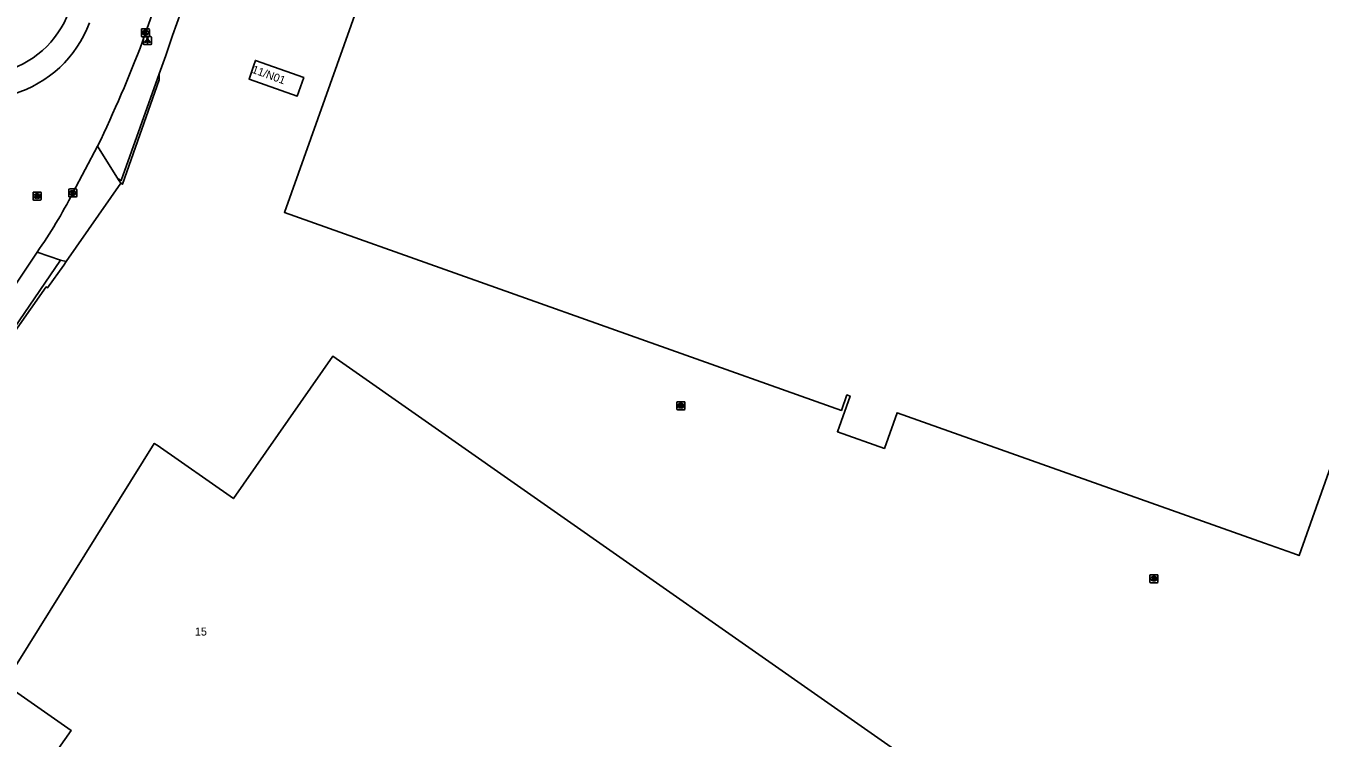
# Model space of a CAD drawing. Extents: x 155018 to 156648, y 383980 to 385733.
# Drawn here: x 155664.5 to 155826.1, y 384797.2 to 384886.2 of the extents above; entities that cross this region are included whole.
import ezdxf

# ---------------------------------------------------------------- set-up
doc = ezdxf.new("R2010")
doc.units = 0
for name, color, linetype in [('IMGEO_Brandkraan', 7, 'Continuous'), ('IMGEO_Groenvoorziening', 7, 'Continuous'), ('IMGEO_Hek', 7, 'Continuous'), ('IMGEO_Kolk', 7, 'Continuous'), ('IMGEO_Lichtpunt', 7, 'Continuous'), ('IMGEO_Pand', 7, 'Continuous'), ('IMGEO_Pand_nummerreeks', 7, 'Continuous'), ('IMGEO_Rijbaan_lokaal_gesloten', 7, 'Continuous'), ('IMGEO_Rijbaan_lokaal_open', 7, 'Continuous'), ('IMGEO_Rioolput', 7, 'Continuous'), ('IMGEO_Voetpad_open', 7, 'Continuous')]:
    doc.layers.add(name, color=color, linetype=linetype)

msp = doc.modelspace()

# ---------------------------------------------------------------- linework, layer by layer
at = {"layer": 'IMGEO_Brandkraan'}
for p, q in [((155745.8, 384838.34), (155745.8, 384839.2)), ((155745.87, 384839.27), (155746.72, 384839.27)), ((155746.28, 384839.05), (155746.31, 384839.05)), ((155746.8, 384839.2), (155746.8, 384838.34)), ((155746.72, 384838.27), (155745.87, 384838.27)), ((155746.31, 384838.49), (155746.28, 384838.49)), ((155804.89, 384816.73), (155804.89, 384817.58)), ((155804.96, 384817.66), (155805.82, 384817.66)), ((155805.82, 384816.66), (155804.96, 384816.66)), ((155805.4, 384816.88), (155805.37, 384816.88)), ((155805.38, 384817.44), (155805.4, 384817.44)), ((155805.89, 384817.58), (155805.89, 384816.73))]:
    msp.add_line(p, q, dxfattribs=at)
for points in [[(155745.8, 384838.34), (155745.8, 384839.2)], [(155745.87, 384839.27), (155746.72, 384839.27)], [(155746.8, 384839.2), (155746.8, 384838.34)], [(155746.72, 384838.27), (155745.87, 384838.27)], [(155746.14, 384838.97), (155746.14, 384838.57), (155746.36, 384838.57)], [(155746.37, 384838.97), (155746.14, 384838.97)], [(155746.32, 384838.89), (155746.27, 384838.89), (155746.27, 384838.81)], [(155746.27, 384838.81), (155746.32, 384838.81)], [(155746.33, 384838.74), (155746.27, 384838.74), (155746.27, 384838.65)], [(155746.27, 384838.65), (155746.33, 384838.65)], [(155804.89, 384816.73), (155804.89, 384817.58)], [(155804.96, 384817.66), (155805.82, 384817.66)], [(155805.82, 384816.66), (155804.96, 384816.66)], [(155805.24, 384817.36), (155805.24, 384816.96), (155805.45, 384816.96)], [(155805.47, 384817.36), (155805.24, 384817.36)], [(155805.42, 384817.27), (155805.36, 384817.27), (155805.36, 384817.2)], [(155805.36, 384817.2), (155805.42, 384817.2)], [(155805.42, 384817.12), (155805.36, 384817.12), (155805.36, 384817.04)], [(155805.36, 384817.04), (155805.42, 384817.04)], [(155805.89, 384817.58), (155805.89, 384816.73)]]:
    msp.add_lwpolyline(points, dxfattribs=at)
for centre, radius, start, end in [((155745.87, 384839.19), 0.0765, 91.552, 178.448), ((155745.87, 384839.19), 0.0765, 91.552, 178.448), ((155746.72, 384839.19), 0.0765, 1.552, 88.448), ((155746.72, 384839.19), 0.0765, 1.552, 88.448), ((155745.87, 384838.34), 0.0765, 181.552, 268.448), ((155745.87, 384838.34), 0.0765, 181.552, 268.448), ((155746.32, 384838.85), 0.0379, 267.8285, 90.9355), ((155746.33, 384838.7), 0.0404, 269.8759, 90.5077), ((155746.36, 384838.82), 0.251, 268.6676, 293.5347), ((155746.38, 384838.82), 0.145, 59.4692, 91.5367), ((155746.4, 384838.87), 0.0922, 285.5137, 58.1501), ((155746.41, 384838.68), 0.105, 301.3115, 78.989), ((155746.72, 384838.34), 0.0765, 271.552, 358.448), ((155746.72, 384838.34), 0.0765, 271.552, 358.448), ((155804.97, 384817.58), 0.0765, 91.552, 178.448), ((155804.97, 384817.58), 0.0765, 91.552, 178.448), ((155804.97, 384816.73), 0.0765, 181.552, 268.448), ((155804.97, 384816.73), 0.0765, 181.552, 268.448), ((155805.42, 384817.24), 0.0379, 267.8285, 90.9355), ((155805.42, 384817.08), 0.0404, 269.8759, 90.5077), ((155805.46, 384817.21), 0.251, 268.6676, 293.5347), ((155805.47, 384817.21), 0.145, 59.4692, 91.5367), ((155805.5, 384817.26), 0.0922, 285.5137, 58.1501), ((155805.5, 384817.07), 0.105, 301.3115, 78.989), ((155805.81, 384817.58), 0.0765, 1.552, 88.448), ((155805.81, 384817.58), 0.0765, 1.552, 88.448), ((155805.81, 384816.73), 0.0765, 271.552, 358.448), ((155805.81, 384816.73), 0.0765, 271.552, 358.448)]:
    msp.add_arc(centre, radius, start, end, dxfattribs=at)
for centre, major_axis, ratio, start_param, end_param in [((155746.28, 384838.77), (-0.387, 0.002), 0.722429, 4.712389, 7.853982), ((155746.31, 384838.77), (-0.39, 0.002), 0.717154, 1.570796, 4.712389), ((155805.38, 384817.16), (-0.387, 0.002), 0.722429, 4.712389, 7.853982), ((155805.4, 384817.16), (-0.39, 0.002), 0.717154, 1.570796, 4.712389)]:
    msp.add_ellipse(centre, major_axis=major_axis, ratio=ratio, start_param=start_param, end_param=end_param, dxfattribs=at)
at = {"layer": 'IMGEO_Groenvoorziening'}
for points in [[(155681.14, 384880.23), (155681.15, 384879.52), (155676.55, 384866.45), (155676.35, 384866.58)], [(155669.5, 384856.8), (155669.21, 384856.33), (155667.2, 384853.51), (155667.02, 384853.62), (155588.11, 384741.16), (155588.22, 384741.11), (155586.79, 384739.09), (155582.63, 384733.19), (155582.42, 384732.89), (155582.32, 384732.95)]]:
    msp.add_lwpolyline(points, dxfattribs=at)
at = {"layer": 'IMGEO_Hek'}
for points in [[(155681.15, 384879.52), (155676.55, 384866.45), (155676.35, 384866.58)], [(155676.35, 384866.58), (155669.5, 384856.8)], [(155586.79, 384739.09), (155588.22, 384741.11), (155588.11, 384741.16), (155667.02, 384853.62), (155667.2, 384853.51), (155669.21, 384856.33)], [(155669.5, 384856.8), (155669.21, 384856.33)]]:
    msp.add_lwpolyline(points, dxfattribs=at)
at = {"layer": 'IMGEO_Kolk'}
for p, q in [((155678.91, 384884.96), (155678.91, 384885.81)), ((155678.98, 384885.89), (155679.83, 384885.89)), ((155679.83, 384884.89), (155678.98, 384884.89)), ((155679.42, 384885.11), (155679.39, 384885.11)), ((155679.4, 384885.67), (155679.42, 384885.67)), ((155679.91, 384885.81), (155679.91, 384884.96)), ((155669.84, 384864.95), (155669.84, 384865.8)), ((155669.91, 384865.87), (155670.76, 384865.87)), ((155670.32, 384865.65), (155670.35, 384865.65)), ((155670.35, 384865.09), (155670.32, 384865.09)), ((155670.84, 384865.8), (155670.84, 384864.95)), ((155670.76, 384864.87), (155669.91, 384864.87))]:
    msp.add_line(p, q, dxfattribs=at)
for points in [[(155678.91, 384884.96), (155678.91, 384885.81)], [(155678.98, 384885.89), (155679.83, 384885.89)], [(155679.83, 384884.89), (155678.98, 384884.89)], [(155679.23, 384885.59), (155679.35, 384885.59), (155679.35, 384885.43), (155679.48, 384885.59), (155679.65, 384885.59), (155679.5, 384885.44), (155679.65, 384885.19), (155679.5, 384885.19), (155679.42, 384885.35), (155679.35, 384885.28), (155679.35, 384885.19), (155679.23, 384885.19), (155679.23, 384885.59)], [(155679.91, 384885.81), (155679.91, 384884.96)], [(155669.84, 384864.95), (155669.84, 384865.8)], [(155669.91, 384865.87), (155670.76, 384865.87)], [(155670.16, 384865.57), (155670.28, 384865.57), (155670.28, 384865.42), (155670.41, 384865.57), (155670.57, 384865.57), (155670.43, 384865.42), (155670.58, 384865.17), (155670.43, 384865.17), (155670.34, 384865.34), (155670.28, 384865.27), (155670.28, 384865.17), (155670.16, 384865.17), (155670.16, 384865.57)], [(155670.84, 384865.8), (155670.84, 384864.95)], [(155670.76, 384864.87), (155669.91, 384864.87)]]:
    msp.add_lwpolyline(points, dxfattribs=at)
for centre, start, end in [((155678.98, 384885.81), 91.552, 178.448), ((155678.98, 384885.81), 91.552, 178.448), ((155678.98, 384884.96), 181.552, 268.448), ((155678.98, 384884.96), 181.552, 268.448), ((155679.83, 384885.81), 1.552, 88.448), ((155679.83, 384885.81), 1.552, 88.448), ((155679.83, 384884.96), 271.552, 358.448), ((155679.83, 384884.96), 271.552, 358.448), ((155669.91, 384865.8), 91.552, 178.448), ((155669.91, 384865.8), 91.552, 178.448), ((155669.91, 384864.95), 181.552, 268.448), ((155669.91, 384864.95), 181.552, 268.448), ((155670.76, 384865.8), 1.552, 88.448), ((155670.76, 384865.8), 1.552, 88.448), ((155670.76, 384864.95), 271.552, 358.448), ((155670.76, 384864.95), 271.552, 358.448)]:
    msp.add_arc(centre, 0.0765, start, end, dxfattribs=at)
for centre, major_axis, ratio, start_param, end_param in [((155679.39, 384885.39), (-0.387, 0.002), 0.722429, 4.712389, 7.853982), ((155679.42, 384885.39), (-0.39, 0.002), 0.717154, 1.570796, 4.712389), ((155670.32, 384865.37), (-0.387, 0.002), 0.722429, 4.712389, 7.853982), ((155670.35, 384865.37), (-0.39, 0.002), 0.717154, 1.570796, 4.712389)]:
    msp.add_ellipse(centre, major_axis=major_axis, ratio=ratio, start_param=start_param, end_param=end_param, dxfattribs=at)
at = {"layer": 'IMGEO_Lichtpunt'}
for p, q in [((155679.17, 384884.8), (155679.17, 384883.99)), ((155679.17, 384884.8), (155679.17, 384883.99)), ((155680.08, 384884.9), (155679.27, 384884.9)), ((155680.08, 384884.9), (155679.27, 384884.9)), ((155680.17, 384883.99), (155680.17, 384884.8)), ((155680.17, 384883.99), (155680.17, 384884.8)), ((155679.27, 384883.9), (155680.08, 384883.9)), ((155679.27, 384883.9), (155680.08, 384883.9))]:
    msp.add_line(p, q, dxfattribs=at)
for points in [[(155679.55, 384884.46), (155679.59, 384884.44), (155679.4, 384884.17), (155679.36, 384884.2), (155679.55, 384884.46)], [(155679.65, 384884.42), (155679.7, 384884.42), (155679.7, 384884.09), (155679.65, 384884.09), (155679.65, 384884.42)], [(155679.76, 384884.44), (155679.8, 384884.46), (155679.99, 384884.2), (155679.95, 384884.17), (155679.76, 384884.44)]]:
    msp.add_lwpolyline(points, dxfattribs=at)
msp.add_circle((155679.67, 384884.6), 0.0994, dxfattribs=at)
for centre, start, end in [((155679.27, 384884.8), 90, 180), ((155679.27, 384884.8), 90, 180), ((155680.08, 384884.8), 0, 90), ((155680.08, 384884.8), 0, 90), ((155679.27, 384883.99), 180, 270), ((155679.27, 384883.99), 180, 270), ((155680.08, 384883.99), 270, 0), ((155680.08, 384883.99), 270, 360)]:
    msp.add_arc(centre, 0.0946, start, end, dxfattribs=at)
at = {"layer": 'IMGEO_Pand'}
for points in [[(155762.36, 385042.82), (155753.18, 385017), (155750.62, 385009.8), (155749.14, 385010.33), (155747.33, 385005.28), (155748.84, 385004.77), (155746.3, 384997.64), (155740.17, 384980.4), (155728.92, 384948.72), (155727.47, 384949.23), (155696.77, 384862.93), (155766.35, 384838.19), (155767.04, 384840.13), (155767.44, 384839.98), (155765.85, 384835.53), (155771.73, 384833.45), (155773.3, 384837.89), (155819.22, 384821.59), (155822.73, 384820.34), (155823.53, 384820.05), (155825.2, 384824.77), (155840.07, 384866.64)], [(155698.98, 384879.19), (155698.38, 384877.48), (155692.36, 384879.59), (155692.96, 384881.34), (155693.16, 384881.93), (155699.2, 384879.79), (155698.98, 384879.19)], [(155662.83, 384787.79), (155670.12, 384798.2), (155661.81, 384804.02), (155680.52, 384834.07), (155680.89, 384833.83), (155690.4, 384827.18), (155702.83, 384844.99), (155791.89, 384782.58)]]:
    msp.add_lwpolyline(points, dxfattribs=at)
at = {"layer": 'IMGEO_Rijbaan_lokaal_gesloten'}
for points in [[(155679.06, 384884.31), (155679.41, 384885.39), (155683.08, 384895.66), (155693.32, 384923.96)], [(155670.34, 384865.37), (155673.44, 384871.22)], [(155586.29, 384744.21), (155590.34, 384750), (155608.17, 384775.45), (155620.85, 384793.57), (155634.39, 384812.92), (155647.78, 384831.99), (155658, 384846.57), (155663.29, 384854.1), (155665.55, 384857.45), (155665.87, 384857.97)]]:
    msp.add_lwpolyline(points, dxfattribs=at)
for centre, radius, start, end in [((155658.65, 384891.78), 14.7, 286.9163, 339.3861), ((155522.65, 384943.7), 167.31, 334.3268, 339.2063), ((155617.4, 384892.23), 59.36, 324.7466, 333.1009)]:
    msp.add_arc(centre, radius, start, end, dxfattribs=at)
at = {"layer": 'IMGEO_Rijbaan_lokaal_open'}
for points in [[(155673.44, 384871.22), (155676.05, 384866.99)], [(155676.35, 384866.58), (155669.5, 384856.8)], [(155676.05, 384866.99), (155676.35, 384866.58)], [(155665.87, 384857.97), (155668.82, 384856.95)], [(155668.82, 384856.95), (155669.5, 384856.8)]]:
    msp.add_lwpolyline(points, dxfattribs=at)
at = {"layer": 'IMGEO_Rioolput'}
for p, q in [((155665.38, 384864.54), (155665.38, 384865.39)), ((155665.46, 384865.47), (155666.31, 384865.47)), ((155665.87, 384865.25), (155665.9, 384865.25)), ((155666.38, 384865.39), (155666.38, 384864.54)), ((155666.31, 384864.47), (155665.46, 384864.47)), ((155665.89, 384864.69), (155665.87, 384864.69))]:
    msp.add_line(p, q, dxfattribs=at)
for points in [[(155665.38, 384864.54), (155665.38, 384865.39)], [(155665.46, 384865.47), (155666.31, 384865.47)], [(155665.97, 384865.16), (155665.72, 384865.17), (155665.72, 384864.77)], [(155665.72, 384864.77), (155665.84, 384864.77), (155665.84, 384864.93), (155665.85, 384864.93)], [(155665.9, 384865.09), (155665.84, 384865.09), (155665.84, 384865)], [(155665.84, 384865), (155665.89, 384865)], [(155665.9, 384864.9), (155665.97, 384864.77), (155666.11, 384864.77), (155666.05, 384864.89)], [(155666.38, 384865.39), (155666.38, 384864.54)], [(155666.31, 384864.47), (155665.46, 384864.47)]]:
    msp.add_lwpolyline(points, dxfattribs=at)
for centre, radius, start, end in [((155665.46, 384865.39), 0.0765, 91.552, 178.448), ((155665.46, 384865.39), 0.0765, 91.552, 178.448), ((155665.85, 384864.88), 0.0533, 26.0293, 88.6989), ((155665.88, 384865.19), 0.19, 274.7715, 282.9687), ((155665.9, 384864.99), 0.0964, 77.0061, 93.1865), ((155665.92, 384865.05), 0.0378, 276.6634, 79.6772), ((155665.97, 384865.05), 0.109, 350.3612, 89.416), ((155665.97, 384865.05), 0.112, 277.5842, 350.9817), ((155665.95, 384864.84), 0.108, 29.5134, 73.7905), ((155666.31, 384865.39), 0.0765, 1.552, 88.448), ((155666.31, 384865.39), 0.0765, 1.552, 88.448), ((155665.46, 384864.54), 0.0765, 181.552, 268.448), ((155665.46, 384864.54), 0.0765, 181.552, 268.448), ((155666.31, 384864.54), 0.0765, 271.552, 358.448), ((155666.31, 384864.54), 0.0765, 271.552, 358.448)]:
    msp.add_arc(centre, radius, start, end, dxfattribs=at)
for centre, major_axis, ratio, start_param, end_param in [((155665.87, 384864.97), (-0.387, 0.002), 0.722429, 4.712389, 7.853982), ((155665.89, 384864.97), (-0.39, 0.002), 0.717154, 1.570796, 4.712389)]:
    msp.add_ellipse(centre, major_axis=major_axis, ratio=ratio, start_param=start_param, end_param=end_param, dxfattribs=at)
at = {"layer": 'IMGEO_Voetpad_open'}
for points in [[(155684.43, 384889.57), (155682.81, 384885.06), (155682.42, 384883.9), (155681.97, 384882.56), (155681.14, 384880.23)], [(155676.05, 384866.99), (155676.09, 384867.1), (155676.37, 384866.91), (155681.14, 384880.23)], [(155668.82, 384856.95), (155660.39, 384844.66), (155636.86, 384811.07), (155608.81, 384771.11), (155594.02, 384750), (155586.65, 384739.49)]]:
    msp.add_lwpolyline(points, dxfattribs=at)
msp.add_arc((155658.61, 384892.11), 11.96, 233.4255, 347.085, dxfattribs=at)

# ---------------------------------------------------------------- texts
at = {"layer": 'IMGEO_Pand_nummerreeks'}
msp.add_text('11/N01', height=1, rotation=340.0169, dxfattribs=at).set_placement((155692.63, 384880.4))
msp.add_text('15', height=1, dxfattribs=at).set_placement((155685.6, 384810.06))

doc.saveas('drawing.dxf')
